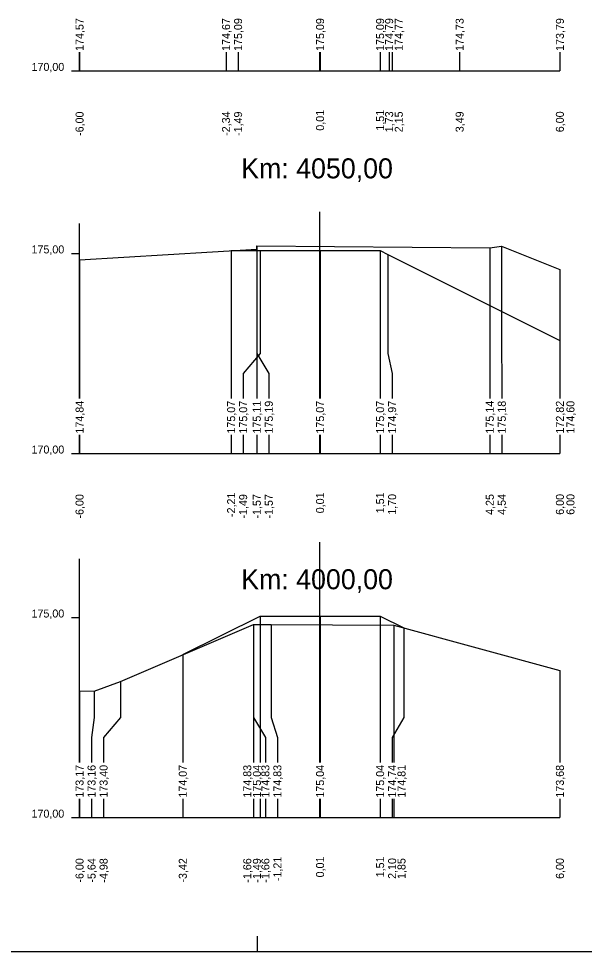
# Model space of a CAD drawing. Extents: x -614174 to -599765, y -1185887 to -1181080.
# Drawn here: x -600991.91 to -600977.78, y -1184533.61 to -1184510.31 of the extents above; entities that cross this region are included whole.
import ezdxf

# ---------------------------------------------------------------- set-up
doc = ezdxf.new("R2010")
doc.units = 0
for name, color, linetype in [('11', 7, 'Continuous'), ('16', 7, 'Continuous'), ('21', 7, 'Continuous'), ('28', 7, 'Continuous'), ('59', 7, 'Continuous'), ('8', 7, 'Continuous'), ('návrh', 7, 'Continuous')]:
    doc.layers.add(name, color=color, linetype=linetype)

msp = doc.modelspace()

# ---------------------------------------------------------------- linework, layer by layer
for points in [[(-600990.389, -1184516.337), (-600985.961, -1184516.066), (-600985.961, -1184515.983), (-600980.141, -1184516.032), (-600979.848, -1184515.993), (-600978.389, -1184516.576)], [(-600986.602, -1184516.105), (-600985.881, -1184516.105), (-600984.381, -1184516.105), (-600982.881, -1184516.105), (-600982.687, -1184516.203), (-600978.389, -1184518.352)], [(-600985.881, -1184516.105), (-600985.881, -1184516.105), (-600985.881, -1184516.105)], [(-600984.381, -1184516.105), (-600984.381, -1184516.105), (-600984.381, -1184516.105)], [(-600982.881, -1184516.105), (-600982.881, -1184516.105), (-600982.881, -1184516.105)], [(-600987.81, -1184526.198), (-600985.881, -1184525.233), (-600984.381, -1184525.233), (-600982.881, -1184525.233), (-600982.286, -1184525.531)], [(-600985.881, -1184525.233), (-600985.881, -1184525.233), (-600985.881, -1184525.233)], [(-600984.381, -1184525.233), (-600984.381, -1184525.233), (-600984.381, -1184525.233)], [(-600982.881, -1184525.233), (-600982.881, -1184525.233), (-600982.881, -1184525.233)], [(-600990.389, -1184527.102), (-600990.027, -1184527.113), (-600989.369, -1184526.867), (-600986.047, -1184525.441), (-600986.046, -1184525.441), (-600985.599, -1184525.442), (-600982.54, -1184525.462), (-600978.389, -1184526.594)], [(-600987.811, -1184526.198), (-600987.81, -1184526.198), (-600987.809, -1184526.197)]]:
    msp.add_lwpolyline(points)
at = {"layer": '11'}
for points in [[(-600990.389, -1184511.146), (-600990.389, -1184511.615)], [(-600986.729, -1184511.146), (-600986.729, -1184511.615)], [(-600986.429, -1184511.146), (-600986.429, -1184511.615)], [(-600984.381, -1184511.146), (-600984.381, -1184511.615)], [(-600982.881, -1184511.146), (-600982.881, -1184511.615)], [(-600982.655, -1184511.146), (-600982.655, -1184511.615)], [(-600982.581, -1184511.146), (-600982.581, -1184511.615)], [(-600980.894, -1184511.146), (-600980.894, -1184511.615)], [(-600978.389, -1184511.146), (-600978.389, -1184511.615)], [(-600985.961, -1184515.983), (-600985.961, -1184518.674), (-600985.661, -1184519.174), (-600985.661, -1184519.796)], [(-600979.848, -1184515.993), (-600979.848, -1184518.674), (-600979.841, -1184519.174), (-600979.841, -1184519.796)], [(-600986.602, -1184516.105), (-600986.602, -1184518.674), (-600986.602, -1184519.174), (-600986.602, -1184519.796)], [(-600985.881, -1184516.105), (-600985.881, -1184518.674), (-600986.302, -1184519.174), (-600986.302, -1184519.796)], [(-600985.961, -1184516.066), (-600985.961, -1184518.674), (-600985.961, -1184519.174), (-600985.961, -1184519.796)], [(-600984.381, -1184516.105), (-600984.381, -1184518.674), (-600984.381, -1184519.174), (-600984.381, -1184519.796)], [(-600982.881, -1184516.105), (-600982.881, -1184518.674), (-600982.881, -1184519.174), (-600982.881, -1184519.796)], [(-600982.687, -1184516.203), (-600982.687, -1184518.674), (-600982.581, -1184519.174), (-600982.581, -1184519.796)], [(-600980.141, -1184516.032), (-600980.141, -1184518.674), (-600980.141, -1184519.174), (-600980.141, -1184519.796)], [(-600990.389, -1184516.337), (-600990.389, -1184518.674), (-600990.389, -1184519.174), (-600990.389, -1184519.796)], [(-600978.389, -1184516.576), (-600978.389, -1184518.674), (-600978.389, -1184519.174), (-600978.389, -1184519.796)], [(-600978.389, -1184518.352), (-600978.389, -1184518.674), (-600978.389, -1184519.174), (-600978.389, -1184519.796)], [(-600990.389, -1184520.704), (-600990.389, -1184521.174)], [(-600986.602, -1184520.704), (-600986.602, -1184521.174)], [(-600986.302, -1184520.704), (-600986.302, -1184521.174)], [(-600985.961, -1184520.704), (-600985.961, -1184521.174)], [(-600985.661, -1184520.704), (-600985.661, -1184521.174)], [(-600984.381, -1184520.704), (-600984.381, -1184521.174)], [(-600982.881, -1184520.704), (-600982.881, -1184521.174)], [(-600982.581, -1184520.704), (-600982.581, -1184521.174)], [(-600980.141, -1184520.704), (-600980.141, -1184521.174)], [(-600979.841, -1184520.704), (-600979.841, -1184521.174)], [(-600978.389, -1184520.704), (-600978.389, -1184521.174)], [(-600978.389, -1184520.704), (-600978.389, -1184521.174)], [(-600985.881, -1184525.233), (-600985.881, -1184527.77), (-600985.881, -1184528.27), (-600985.881, -1184528.892)], [(-600984.381, -1184525.233), (-600984.381, -1184527.77), (-600984.381, -1184528.27), (-600984.381, -1184528.892)], [(-600982.881, -1184525.233), (-600982.881, -1184527.77), (-600982.881, -1184528.27), (-600982.881, -1184528.892)], [(-600986.047, -1184525.441), (-600986.047, -1184527.77), (-600986.047, -1184528.27), (-600986.047, -1184528.892)], [(-600986.046, -1184525.441), (-600986.046, -1184527.77), (-600985.747, -1184528.27), (-600985.747, -1184528.892)], [(-600985.599, -1184525.442), (-600985.599, -1184527.77), (-600985.447, -1184528.27), (-600985.447, -1184528.892)], [(-600982.286, -1184525.531), (-600982.286, -1184527.77), (-600982.581, -1184528.27), (-600982.581, -1184528.892)], [(-600982.54, -1184525.462), (-600982.54, -1184527.77), (-600982.54, -1184528.27), (-600982.54, -1184528.892)], [(-600987.81, -1184526.198), (-600987.81, -1184527.77), (-600987.81, -1184528.27), (-600987.81, -1184528.892)], [(-600978.389, -1184526.594), (-600978.389, -1184527.77), (-600978.389, -1184528.27), (-600978.389, -1184528.892)], [(-600989.369, -1184526.867), (-600989.369, -1184527.77), (-600989.789, -1184528.27), (-600989.789, -1184528.892)], [(-600990.389, -1184527.102), (-600990.389, -1184527.77), (-600990.389, -1184528.27), (-600990.389, -1184528.892)], [(-600990.027, -1184527.113), (-600990.027, -1184527.77), (-600990.089, -1184528.27), (-600990.089, -1184528.892)], [(-600990.389, -1184529.8), (-600990.389, -1184530.27)], [(-600990.089, -1184529.8), (-600990.089, -1184530.27)], [(-600989.789, -1184529.8), (-600989.789, -1184530.27)], [(-600987.81, -1184529.8), (-600987.81, -1184530.27)], [(-600986.047, -1184529.8), (-600986.047, -1184530.27)], [(-600985.881, -1184529.8), (-600985.881, -1184530.27)], [(-600985.747, -1184529.8), (-600985.747, -1184530.27)], [(-600985.447, -1184529.8), (-600985.447, -1184530.27)], [(-600984.381, -1184529.8), (-600984.381, -1184530.27)], [(-600982.881, -1184529.8), (-600982.881, -1184530.27)], [(-600982.581, -1184529.8), (-600982.581, -1184530.27)], [(-600982.54, -1184529.8), (-600982.54, -1184530.27)], [(-600978.389, -1184529.8), (-600978.389, -1184530.27)]]:
    msp.add_lwpolyline(points, dxfattribs=at)
at = {"layer": '16'}
for p, q in [((-600990.389, -1184511.615), (-600978.389, -1184511.615)), ((-600990.389, -1184521.174), (-600978.389, -1184521.174)), ((-600990.389, -1184530.27), (-600978.389, -1184530.27))]:
    msp.add_line(p, q, dxfattribs=at)
msp.add_lwpolyline([(-600982.285, -1184525.531), (-600982.286, -1184525.531), (-600982.286, -1184525.531)], dxfattribs=at)
at = {"layer": '21'}
for p, q in [((-600990.589, -1184511.615), (-600990.389, -1184511.615)), ((-600990.589, -1184516.174), (-600990.389, -1184516.174)), ((-600990.589, -1184521.174), (-600990.389, -1184521.174)), ((-600990.589, -1184525.27), (-600990.389, -1184525.27)), ((-600990.589, -1184530.27), (-600990.389, -1184530.27))]:
    msp.add_line(p, q, dxfattribs=at)
at = {"layer": '28'}
for p, q in [((-600984.389, -1184511.615), (-600984.389, -1184511.146)), ((-600984.389, -1184519.796), (-600984.389, -1184515.135)), ((-600984.389, -1184521.174), (-600984.389, -1184520.704)), ((-600984.389, -1184528.892), (-600984.389, -1184523.384)), ((-600984.389, -1184530.27), (-600984.389, -1184529.8))]:
    msp.add_line(p, q, dxfattribs=at)
at = {"layer": '8'}
for p, q in [((-600990.389, -1184511.615), (-600990.389, -1184511.146)), ((-600990.389, -1184519.796), (-600990.389, -1184515.429)), ((-600990.389, -1184521.174), (-600990.389, -1184520.704)), ((-600990.389, -1184528.892), (-600990.389, -1184523.806)), ((-600990.389, -1184530.27), (-600990.389, -1184529.8))]:
    msp.add_line(p, q, dxfattribs=at)
at = {"layer": 'návrh'}
for p, q in [((-600985.944, -1184533.61), (-600985.944, -1184533.23)), ((-601006.944, -1184533.61), (-600985.944, -1184533.61)), ((-600985.944, -1184533.61), (-600964.944, -1184533.61))]:
    msp.add_line(p, q, dxfattribs=at)

# ---------------------------------------------------------------- texts
msp.add_text('+', height=0.001).set_placement((-600986.602, -1184516.106))
at = {"layer": '16'}
for s, p in [('174,57', (-600990.289, -1184511.115)), ('174,67', (-600986.629, -1184511.115)), ('175,09', (-600986.329, -1184511.115)), ('175,09', (-600984.281, -1184511.115)), ('175,09', (-600982.781, -1184511.115)), ('174,79', (-600982.555, -1184511.115)), ('174,77', (-600982.315, -1184511.115)), ('174,73', (-600980.794, -1184511.115)), ('173,79', (-600978.289, -1184511.115)), ('174,84', (-600990.289, -1184520.674)), ('175,07', (-600986.502, -1184520.674)), ('175,07', (-600986.202, -1184520.674)), ('175,11', (-600985.861, -1184520.674)), ('175,19', (-600985.561, -1184520.674)), ('175,07', (-600984.281, -1184520.674)), ('175,07', (-600982.781, -1184520.674)), ('174,97', (-600982.481, -1184520.674)), ('175,14', (-600980.041, -1184520.674)), ('175,18', (-600979.741, -1184520.674)), ('172,82', (-600978.289, -1184520.674)), ('174,60', (-600978.026, -1184520.674)), ('173,17', (-600990.289, -1184529.77)), ('173,16', (-600989.989, -1184529.77)), ('173,40', (-600989.689, -1184529.77)), ('174,07', (-600987.71, -1184529.77)), ('174,83', (-600986.099, -1184529.77)), ('175,04', (-600985.858, -1184529.77)), ('174,83', (-600985.647, -1184529.77)), ('174,83', (-600985.347, -1184529.77)), ('175,04', (-600984.281, -1184529.77)), ('175,04', (-600982.781, -1184529.77)), ('174,74', (-600982.481, -1184529.77)), ('174,81', (-600982.246, -1184529.77)), ('173,68', (-600978.289, -1184529.77))]:
    msp.add_text(s, height=0.2, rotation=90, dxfattribs=at).set_placement(p)
at = {"layer": '21'}
for s, p in [('170,00', (-600991.589, -1184511.615)), ('175,00', (-600991.589, -1184516.174)), ('170,00', (-600991.589, -1184521.174)), ('175,00', (-600991.589, -1184525.27)), ('170,00', (-600991.589, -1184530.27))]:
    msp.add_text(s, height=0.2, dxfattribs=at).set_placement(p)
at = {"layer": '28'}
for s, p in [('Km: 4050,00', (-600986.352, -1184514.299)), ('Km: 4000,00', (-600986.352, -1184524.564))]:
    msp.add_text(s, height=0.5, dxfattribs=at).set_placement(p)
at = {"layer": '59'}
for s, p in [('-6,00', (-600990.289, -1184513.239)), ('-2,34', (-600986.629, -1184513.238)), ('-1,49', (-600986.329, -1184513.24)), ('0,01', (-600984.281, -1184513.108)), ('1,51', (-600982.781, -1184513.108)), ('1,73', (-600982.555, -1184513.146)), ('2,15', (-600982.315, -1184513.148)), ('3,49', (-600980.794, -1184513.147)), ('6,00', (-600978.289, -1184513.146)), ('-6,00', (-600990.289, -1184522.797)), ('-2,21', (-600986.502, -1184522.759)), ('-1,49', (-600986.202, -1184522.798)), ('-1,57', (-600985.861, -1184522.797)), ('-1,57', (-600985.561, -1184522.797)), ('0,01', (-600984.281, -1184522.666)), ('1,51', (-600982.781, -1184522.666)), ('1,70', (-600982.481, -1184522.704)), ('4,25', (-600980.041, -1184522.706)), ('4,54', (-600979.741, -1184522.704)), ('6,00', (-600978.289, -1184522.704)), ('6,00', (-600978.026, -1184522.704)), ('-6,00', (-600990.289, -1184531.893)), ('-5,64', (-600989.989, -1184531.893)), ('-4,98', (-600989.689, -1184531.894)), ('-3,42', (-600987.71, -1184531.892)), ('-1,66', (-600986.099, -1184531.894)), ('-1,49', (-600985.858, -1184531.894)), ('-1,66', (-600985.647, -1184531.894)), ('-1,21', (-600985.347, -1184531.855)), ('0,01', (-600984.281, -1184531.762)), ('1,51', (-600982.781, -1184531.762)), ('2,10', (-600982.481, -1184531.8)), ('1,85', (-600982.246, -1184531.802)), ('6,00', (-600978.289, -1184531.8))]:
    msp.add_text(s, height=0.2, rotation=90, dxfattribs=at).set_placement(p)

doc.saveas('drawing.dxf')
